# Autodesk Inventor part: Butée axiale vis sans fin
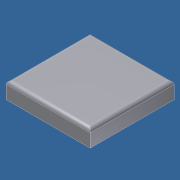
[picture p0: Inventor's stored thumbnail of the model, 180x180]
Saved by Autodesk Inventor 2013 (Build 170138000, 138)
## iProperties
Created: 2011-10
Part Number: Butée axiale vis sans fin
Material: Acier allié
Document SubType Name: Modeling
Designer: Laur
Mass: 0.204179 g
Surface Area: 0.7242 cm^2
Volume: 0.02601 cm^3
Density: 7.85 g/cm^3
Author: Laur
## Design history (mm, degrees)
sketch "Esquisse1"
  geometry: L1 (-2.55, 2.55)-(-2.55, -2.55) reference; L2 (-2.55, -2.55)-(2.55, -2.55) reference; L3 (2.55, -2.55)-(2.55, 2.55) reference; L4 (2.55, 2.55)-(-2.55, 2.55) reference; C1 r 1.98 at (0.022, -0.03) reference
extrude "épaisseur 1 mm" new body sketch "Esquisse1" distance "d0" = 1; taper "d1" = 0 deg
fillet "Congé 0,2" dims "d2" = 0.2
node "Solide1"
node "Corps solides"
node "Corps surfaciques"
node "Référence1"
